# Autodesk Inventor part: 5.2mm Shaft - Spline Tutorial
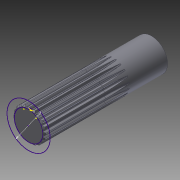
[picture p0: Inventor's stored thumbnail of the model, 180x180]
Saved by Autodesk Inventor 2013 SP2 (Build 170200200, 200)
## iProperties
Created: 2020-02
Part Number: 5.2mm Shaft - Spline Tutorial
Material: Steel
Document SubType Name: Modeling
Designer: DELL
Density: 1 g/cm^3
CustomPartVersion: 1
Author: DELL
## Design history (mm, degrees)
sketch "Sketch3"
  geometry: C1 r 2.6 at (0, 0); 1 further point
  constraints: 1 centre point, 1 coincident
  dimensions: "d16" = 5.2 diameter of C1
extrude "Extrusion1" new body sketch "Sketch3" distance "d18" = 20; taper "d19" = 0 deg
chamfer "Chamfer4" distance "d21" = 0.25; stored, may be unused: second distance "d22" = 2, angle "d23" = 45 deg
sketch "Sketch4"
  geometry: L1 (0, 0)-(1.12, 2.704); L2 (0, -3.751)-(0, 3.779) reference; L3 (0, 0)-(-1.12, 2.704); L4 (0.643, 1.552)-(-1.571, 2.469); C1 r 2.375 at (0, 0); C2 r 2.475 at (0, 0); C3 r 2.183 at (0, 0); C4 r 1.68 at (0, 0); 1 further point
  constraints: 6 end point, 4 centre point, 4 coincident, 1 perpendicular, 1 point on line, 1 tangent
  dimensions: "d46" = 4.75 diameter of C1; "d48" = 4.95 diameter of C2; "d49" = 4.367 diameter of C3; "d50" = 3.359 diameter of C4; "d52" = 22.5 deg angle of L1 L2; "d53" = 45 deg angle of L1 L3
sketch "Sketch5"
  geometry: L1 (0, -1.686)-(-0.333, -2.668); L2 (0, -1.686)-(0.336, -2.675); L3 (0, -3.751)-(0, 3.779) reference; 5 further points
  constraints: 4 end point, 2 other
  dimensions: "d54" = 1.6862 distance of L1.start point (0, 0); "d55" = 18.75 deg angle of L2 L3; "d56" = 18.75 deg angle of L3 L1 (= d55); "d57" = 37.5 deg angle of L2 L1 (derived)
node "Involute Splining9"
sketch "Sketch6"
  geometry: C1 r 3.5 at (0, 0); A1 r 2.308 centre (0, 0) between (0.414, 2.271) and (0.308, 2.287) reference; A2 r 1.037 centre (-0.708, 1.95) between (0.259, 2.327) and (0.255, 2.336) reference; A3 r 0.063 centre (0.317, 2.349) between (0.259, 2.327) and (0.308, 2.287) reference; A4 r 0.062 centre (0.425, 2.332) between (0.414, 2.271) and (0.473, 2.293) reference; A5 r 1.037 centre (1.276, 1.636) between (0.48, 2.301) and (0.473, 2.293) reference; A6 r 1.037 centre (1.276, 1.636) between (0.706, 2.502) and (0.473, 2.293) reference; A7 r 2.6 centre (0, 0) between (0.706, 2.502) and (0.102, 2.598); 2 further points
  constraints: 3 coincident, 2 centre point, 2 point on circle, 4 other
  dimensions: "d61" = 7 diameter of C1
body "Solid2"
feature "Shaft Groove"
